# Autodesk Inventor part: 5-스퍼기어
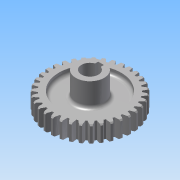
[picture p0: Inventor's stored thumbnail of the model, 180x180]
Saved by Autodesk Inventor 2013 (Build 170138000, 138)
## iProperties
Created: 2013-08
Part Number: 5-스퍼기어
Material: 강
Document SubType Name: Modeling
Designer: 한국산업디자인학원
Categories: <?xml version="1.0" encoding="UTF-16"?> <MemberInstance><Categories><FamilyTemplate><FamilyTemplateParameter ValueType="xs:double" Id="1" ObjectReferenceKey="da
Density: 1 g/cm^3
CustomPartVersion: 1
Author: 한국산업디자인학원
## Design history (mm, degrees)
sketch "Sketch1"
  geometry: C1 r 37 at (0, 0)
  constraints: 1 centre point
  dimensions: "d0" = 74 diameter of C1 (= da_da)
extrude "Extrusion1" new body sketch "Sketch1" distance "d1" = 15 (= da_b); taper "d2" = 0 deg
chamfer "모따기1" distance "d49" = 1; stored, may be unused: second distance "d50" = 2, angle "d51" = 45 deg
workplane "Work Plane2"
feature "피치 지름" dims "d4" = 10, "d5" = 0
workplane "Work Plane8"
workplane "Work Plane9"
sketch "스케치3"
  geometry: C1 r 36 at (0, 0) reference; C2 r 27.5 at (0, 0); C3 r 12.5 at (0, 0)
  constraints: 2 centre point, 2 coincident
  dimensions: "d52" = 55 diameter of C2; "d54" = 25 diameter of C3
extrude "돌출2" cut sketch "스케치3" distance "d55" = 5; taper "d56" = 0 deg
sketch "스케치4"
  geometry: C1 r 36 at (0, 0) reference; C2 r 27.5 at (0, 0); C3 r 12.5 at (0, 0)
  constraints: 2 centre point, 2 coincident
  dimensions: "d57" = 55 diameter of C2; "d59" = 25 diameter of C3
extrude "돌출3" cut sketch "스케치4" distance "d60" = 5; taper "d61" = 0 deg
node "작업 평면11"
sketch "스케치6"
  geometry: C1 r 12.5 at (0, 0) reference; 1 further point
extrude "돌출5" join sketch "스케치6" stored distance "d78" = 5; taper "d79" = 0 deg
hole "구멍1" diameter "d64" = 15; stored, may be unused: countersink angle "d68" = 90 deg, drill point angle "d70" = 118 deg; dims "d62" = 10, "d63" = 10, "d65" = 6, "d66" = 4, "d67" = 2, "d69" = 8
hole "구멍2" diameter "d82" = 15; stored, may be unused: countersink angle "d86" = 90 deg, drill point angle "d88" = 118 deg; dims "d80" = 10, "d81" = 10, "d83" = 6, "d84" = 4, "d85" = 2, "d87" = 8
sketch "스케치8"
  geometry: L1 (-2.5, 9.8)-(2.5, 9.8); L2 (2.5, 9.8)-(2.5, 7.071); L3 (-2.5, 7.071)-(-2.5, 9.8); A1 r 7.5 centre (0, 0) between (2.5, 7.071) and (-2.5, 7.071) reference; A2 r 7.5 centre (0, 0) between (2.5, 7.071) and (-2.5, 7.071); 1 further point
  constraints: 6 end point, 6 point on circle, 1 centre point, 1 concentric, 1 horizontal, 1 midpoint, 1 parallel, 1 perpendicular, 1 vertical alignment
  dimensions: "d89" = 5 distance of L1.start L1.end; "d91" = 17.3 dimension on A1 L1
extrude "돌출6" cut sketch "스케치8" stored distance "d92" = 5; taper "d93" = 0 deg
feature "스퍼 기어" dims "da_b" = 15, "da_d" = 70, "da_aw" = 70, "da_da" = 74, "da_df" = 65, "da_dw" = 70, angle "da_beta" = 0 deg, "da_lefttooth" = 0, "da_righttooth" = 0
fillet "모깎기1" dims "d76" = 3
body "Solid1"
sketch "Sketch2"
  geometry: C1 r 37 at (0, 0) reference; C2 r 35 at (0, 0)
  constraints: 1 centre point, 1 coincident
  dimensions: "d3" = 70 diameter of C2 (= da_dw)
body "Srf1"
node "투영된 루프1"
other parameters: "d17" = 0, "d34" = 0.8976 (computed from da_z), "d39" = 0, "d41" = 0, "d47" = 0, "d48" = 0, "d77" = 31
